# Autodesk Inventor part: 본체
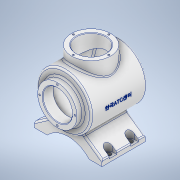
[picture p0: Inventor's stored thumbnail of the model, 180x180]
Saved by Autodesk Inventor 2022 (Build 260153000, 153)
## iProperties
Created: 2023-04
Part Number: 본체
Material: 알루미늄 6061
Document SubType Name: Modeling
Designer: Admin
Mass: 1321.72 g
Surface Area: 1086.45 cm^2
Volume: 489.527 cm^3
Density: 2.7 g/cm^3
Appearance: 알루미늄 - 평지
Author: Admin
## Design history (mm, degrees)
sketch "스케치5"
  geometry: L1 (0, -10.683)-(0, 64.095) reference; L2 (-86.8, 0)-(86.8, 0) reference; L3 (-62, 0)-(-62, 10); L4 (-62, 10)-(0, 53.413); L5 (0, 53.413)-(62, 10); L6 (62, 10)-(62, 0); L7 (-62, 0)-(62, 0); 1 further point
  constraints: 10 end point, 3 point on line, 2 perpendicular, 1 vertical
  dimensions: "d21" = 10 distance of L5.end L6.end; "d22" = 10 distance of L3.start L3.end; "d23" = 55 deg angle of L4 L3; "d24" = 55 deg angle of L6 L5; "d25" = 124 distance between parallel lines of L3 L6
extrude "돌출2" new body sketch "스케치5" stored distance "d26" = 80; taper "d27" = 0 deg
sketch "스케치6"
  geometry: L1 (77, 101)-(77, -97); L2 (0, -40)-(0, 40) reference; L3 (77, 60)-(113, 60); L4 (113, 60)-(113, 48); L5 (113, 48)-(127, 48); L6 (127, 48)-(127, -54.4); L7 (53.413, 40)-(10, 40) reference; A1 r 226 centre (77, 166) between (77, -60) and (127, -54.4); 1 further point
  constraints: 10 end point, 3 perpendicular, 3 point on line, 2 point on circle, 1 centre point, 1 horizontal, 1 vertical
  dimensions: "d28" = 77 distance between parallel lines of L2 L1; "d29" = 226 radius of A1; "d30" = 20 distance between parallel lines of L7 L3; "d31" = 72 diameter of L4 L1; "d32" = 100 diameter of L6 L1; "d33" = 12 distance of L3.end L4.end; "d34" = 120 distance from line of L3 A1.start
revolve "회전1" sketch "스케치6" stored, may be unused: angle "d35" = 90 deg
node "작업 평면1"
sketch "스케치7"
  geometry: L1 (0, -84)-(0, 84) reference; L2 (86.8, 0)-(-86.8, 0) reference; L3 (-36, 60)-(36, 60) reference; C1 r 36 at (0, -2); 1 further point
  constraints: 1 centre point, 1 point on line
  dimensions: "d37" = 72 diameter of C1; "d38" = 62 distance from line of L3 C1.centre
extrude "돌출3" join sketch "스케치7" stored distance "d39" = 80; taper "d40" = 0 deg
sketch "스케치8"
  geometry: C1 r 36 at (0, 0) reference; C2 r 27 at (0, 0); 1 further point
  constraints: 1 centre point, 1 coincident
  dimensions: "d41" = 54 diameter of C2
extrude "돌출4" cut sketch "스케치8" distance "d42" = 50; taper "d43" = 0 deg
sketch "스케치9"
  geometry: L1 (41, 60)-(113, 60) reference; L2 (77, 60)-(77, -67.76); L3 (77, 60)-(104, 60); L4 (104, 60)-(104, 41); L5 (104, 41)-(77, 41); L6 (77, 41)-(77, 60); L7 (77, 41)-(120, 41); L8 (120, 41)-(120, -48.737); L9 (77, -41)-(77, 41); L10 (127, 48)-(127, -54.4) reference; A1 r 226 centre (77, 166) between (27, -54.4) and (127, -54.4) reference; A2 r 219 centre (77, 166) between (77, -53) and (120, -48.737); 3 further points
  constraints: 16 end point, 3 parallel, 2 horizontal, 2 perpendicular, 2 point on circle, 1 centre point, 1 midpoint, 1 point on line, 1 vertical
  dimensions: "d46" = 7 radial gap between concentric circles of A1 A2; "d47" = 19 distance between parallel lines of L5 L1; "d48" = 86 diameter of L8 L2; "d49" = 54 diameter of L4 L2
revolve "회전2" sketch "스케치9" stored, may be unused: angle "d50" = 90 deg
sketch "스케치10" dims "d51" = 65
  geometry: L1 (0, 82)-(0, -86) reference; C1 r 27 at (0, 0) reference; 3 further points
  constraints: 1 coincident, 1 vertical alignment, 2 other
hole "구멍1" sketch "스케치10" at (0, 32.5) diameter "d52" = 3.242; stored, may be unused: countersink angle "d56" = 90 deg, drill point angle "d58" = 118 deg; dims "d53" = 8, "d54" = 4, "d55" = 2, "d57" = 10
sketch "스케치11" dims "d62" = 65
  geometry: L1 (0, -105.4)-(0, 93.4) reference; C1 r 36 at (0, 0) reference; 3 further points
  constraints: 1 coincident, 1 point on line, 1 vertical alignment, 2 other
hole "구멍2" sketch "스케치11" at (0, 32.5) diameter "d63" = 3.242; stored, may be unused: countersink angle "d67" = 90 deg, drill point angle "d69" = 118 deg; dims "d64" = 8, "d65" = 4, "d66" = 2, "d68" = 10
node "작업 평면2"
node "작업 평면3"
sketch "스케치14"
  geometry: L1 (41, 60)-(113, 60) reference; L2 (77, 60)-(77, -71); 2 further points
  constraints: 2 end point, 1 midpoint, 1 point on line, 1 vertical, 1 other
  dimensions: "d89" = 62 distance from line of L1 point (77, -2)
feature "엠보싱1" sketch "스케치14" dims "d90" = 0.5, "d91" = 0
sketch "스케치15"
  geometry: L1 (0, -28.4)-(0, 170.4) reference; L2 (-86.8, 0)-(86.8, 0) reference; L3 (62, 0)-(-62, 0) reference; L4 (-38.5, 0)-(38.5, 0); A1 r 52.096 centre (0, -35.096) between (38.5, 0) and (0, 17); A2 r 52.096 centre (0, -35.096) between (0, 17) and (-38.5, 0); 1 further point
  constraints: 4 point on circle, 2 centre point, 2 end point, 2 point on line, 1 collinear, 1 symmetric about line, 1 other
  dimensions: "d96" = 77 distance of L4.end L4.start; "d97" = 17 distance of point (0, 0) A1.end
extrude "돌출5" cut sketch "스케치15" extent not by distance; stored distance "d98" = 0; taper "d99" = 0 deg
node "작업 평면5"
sketch "스케치17"
  geometry: L1 (-62, -40)-(-62, 40) reference; L2 (62, -40)-(62, 40) reference; L3 (62, -40)-(26.694, -40) reference; 5 further points
  constraints: 2 horizontal alignment, 2 vertical alignment
  dimensions: "d106" = 8 distance from line of L1 point (-54, -20); "d107" = 8 distance from line of L2 point (54, -20); "d108" = 20 distance from line of L3 point (54, -20); "d109" = 40 distance of point (54, -20) point (54, 20)
hole "구멍4" sketch "스케치17" at (54, -20), (-54, -20), (-54, 20), (54, 20) diameter "d110" = 9; stored, may be unused: countersink angle "d114" = 90 deg, drill point angle "d116" = 0 deg; dims "d111" = 6, "d112" = 14, "d113" = 24, "d115" = 30
sketch "스케치18"
  geometry: L1 (0, 7)-(13, 7); L2 (0, -7)-(13, -7); L3 (13, -7)-(13, 7); L4 (0, 7)-(0, -7); L5 (-147.8, 20)-(39.8, 20) reference; L6 (-54, 104)-(-54, -64) reference; L7 (0, 33)-(13, 33); L8 (0, 33)-(0, 47); L9 (0, 47)-(13, 47); L10 (13, 47)-(13, 33); L11 (-121, 47)-(-121, 33); L12 (-108, 47)-(-121, 47); L13 (-108, 33)-(-108, 47); L14 (-108, 33)-(-121, 33); L15 (-108, 7)-(-121, 7); L16 (-121, -7)-(-121, 7); L17 (-108, -7)-(-121, -7); L18 (-108, 7)-(-108, -7); A1 r 7 centre (0, 0) between (0, 7) and (0, -7) reference; 1 further point
  constraints: 32 end point, 12 symmetric about line, 2 horizontal, 2 point on circle, 2 tangent, 2 vertical, 1 perpendicular
  dimensions: "d117" = 13 distance between parallel lines of L13 L11
extrude "돌출6" cut sketch "스케치18" extent not by distance; stored distance "d118" = 0; taper "d119" = 0 deg
fillet "모깎기1" dims "d120" = 3
fillet "모깎기2" dims "d121" = 3
chamfer "모따기1" distance "d122" = 1; stored, may be unused: second distance "d123" = 2, angle "d124" = 45 deg
fillet "모깎기3" dims "d125" = 3
node "솔리드2"
pattern_circular "원형 패턴1" dims angle "d60" = 360 deg
pattern_circular "원형 패턴2" dims angle "d71" = 360 deg
feature "A9D066F2-1C7D-4E18-AEED-F7BC21143FA4" dims "d110" = 9, "d111" = 6, "d112" = 14, "d113" = 24, "d114" = 90 deg, "d115" = 30, "d116" = 0
other parameters: "d36" = 142, "d73" = 45, "d88" = 314
